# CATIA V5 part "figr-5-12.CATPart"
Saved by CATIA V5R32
Part number: Part1
Bounding box of the stored display mesh (mm): x 0 to 150, y -70 to 70, z -150 to 69.804
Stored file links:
  D:\PROJECTS\Project 2022\CATIA V5 6R 2022\Resources\Part Files\c05_catia_v5_6r2022_prt\figr-5-12.CATPart
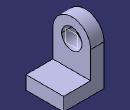
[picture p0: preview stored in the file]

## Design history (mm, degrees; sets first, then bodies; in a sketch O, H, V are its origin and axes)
Set1
  Plane1: type 1Curve, Element1 edge [face of Pad1 | face of Pad1]
Body1 (main body)
  Sketch1 on yz-plane, origin (0, 0, 0), H (0, 1, 0), V (0, 0, 1)
    arc A1 centre (0, 0) radius 70 from (70, 0) to (-70, 0) ccw
    point P1 (70, 0)
    point P2 (-70, 0)
    line L1 (-70, 0) -> (-70, -150)
    line L2 (-70, -150) -> (70, -150)
    line L3 (70, -150) -> (70, 0)
    circle A2 centre (0, 0) radius 37.5
    radius A1 = 70
    radius A2 = 37.5
    distance O L2 = 150
    coincidence: P1 H, P2 H
    tangency: L1 A1, L3 A1
    horizontal: L2 H
  Pad1: profile Sketch1, direction (1, 0, 0), length 50
  Sketch2 on face of Pad1, origin (50, 0, 0), H (0, 1, 0), V (0, 0, 1)
    line L1 (-70, -150) -> (70, -150)
    line L2 (70, -150) -> (70, -100)
    line L3 (70, -100) -> (-70, -100)
    line L4 (-70, -100) -> (-70, -150)
    reference projected line E1 (-70, -150) -> (70, -150) from edge [face of Pad1 | face of Pad1]
    reference projected line E2 (-70, 0) -> (-70, -150) from edge [face of Pad1 | face of Pad1]
    reference projected line E3 (70, -150) -> (70, 0) from edge [face of Pad1 | face of Pad1]
    length L2 = 50
    horizontal: L1 H, L3 H
    vertical: L2 V, L4 V
    coincidence: L1 E1, E2 L4, L2 E3
  Pad2: profile Sketch2, direction (1, 0, 0), length 100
